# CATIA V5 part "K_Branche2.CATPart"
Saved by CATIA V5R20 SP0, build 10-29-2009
Part number: Branche2
Bounding box of the stored display mesh (mm): x -28.5 to -13.5, y -176.797 to 60, z -107.389 to 48.468
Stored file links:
  G:\Khaled_CFAO_2011\SIL\SIL_GR1\mneves\Khaled\CAD_CATIA_Modifie\K_Branche2.CATPart
  G:\Khaled_CFAO_2011\SIL\SIL_GR1\mneves\Khaled\CAD_CATIA_Modifie\K_AssPince_A_Bois.CATProduct
  G:\Khaled_CFAO_2011\SIL\SIL_GR1\mneves\Khaled\CAD_CATIA\Branche1.CATPart
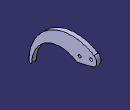
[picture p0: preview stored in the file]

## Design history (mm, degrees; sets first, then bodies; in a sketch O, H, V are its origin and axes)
External parameters (linked from other documents)
  External.Distance_Inter_Pivot = 200 mm
  External.Rayon_Pivot = 5 mm
  External.Epaisseur_Branche = 15 mm
  External.Distance_Inter_Pivot.1 = 200 mm
Set1
  Plane1 "Plan_Branche2": linked copy from another document
  Point1 "Centre_Pivot_Branche2": linked copy from another document
  Point2 "Centre_Pivot_Branche2": linked copy from another document
  Point3: linked copy from another document
  Line1: linked copy from another document
Body1 (main body)
  Sketch1 on Plane1, origin (-13.5, 0, 0), H (0, 1, 0), V (0, 0, 1)
    line L1 (44.8507, -9.4029) -> (-9.7014, -23.0409)
    point P1 (-9.7014, -23.0409)
    arc A1 centre (40, 10) radius 20 from (44.8507, -9.4029) to (50.2769, 27.1577) ccw
    point P3 (40, 10)
    arc A2 centre (-171.7973, -102.3997) radius 5 from (-176.7972, -102.4298) to (-166.799, -102.5289) ccw
    point P5 (-171.7973, -102.3997)
    point P6 (-166.799, -102.5289)
    point P7 (-166.799, -102.5289)
    arc A3 centre (-66.8324, -105.1143) radius 100 from (-166.799, -102.5289) to (-9.7014, -23.0409) cw
    point P9 (-9.7014, -23.0409)
    arc A4 centre (-26.7999, -101.5247) radius 150 from (-176.7972, -102.4298) to (50.2769, 27.1577) cw
    point P11 (50.2769, 27.1577)
    circle A5 centre (40, 10) radius 5
    point P12 (40, 10)
    circle A6 centre (0, 0) radius 5
    point P13 (0, 0)
    reference projected point E1 (0, 0) from Point2
    reference projected point E2 (0, 0) from Point2
    reference projected point E3 (40, 10) from Point3
    reference projected point E4 (40, 10) from Point3
    reference projected point E5 (0, 0) from Point2
    reference projected point E6 (0, 0) from Point2
    reference projected line E7 (0, 0) -> (40, 10) from Line1
    radius A2 = 5 {= External.Distance_Inter_Pivot.1 /40}
    radius A5 = 5 {= External.Distance_Inter_Pivot.1 /40}
    radius A6 = 5 {= External.Distance_Inter_Pivot.1  /40}
    radius A3 = 100 {= External.Distance_Inter_Pivot.1 /2}
    radius A4 = 150 {= (3/4)*External.Distance_Inter_Pivot.1}
    distance E1 P5 = 200 {= External.Distance_Inter_Pivot.1}
    distance E2 P11 = 57.1429 {= External.Distance_Inter_Pivot.1  /3.5}
    distance P1 E6 = 25 {= External.Distance_Inter_Pivot.1  /8}
    distance L1 E7 = 20 {= External.Distance_Inter_Pivot.1 /10}
    tangency: A1 L1, A3 A2, A1 A4, A4 A2
    coincidence: P6 P7, P1 P9, P12 E3, P3 E4, E5 P13
  Pad1: profile Sketch1, direction (-1, 0, 0), length 15 {= External.Epaisseur_Branche}
  Fillet1: radius 5, on edge [face of Pad1 from Sketch1.A3 | face of Pad1 from Sketch1.L1]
